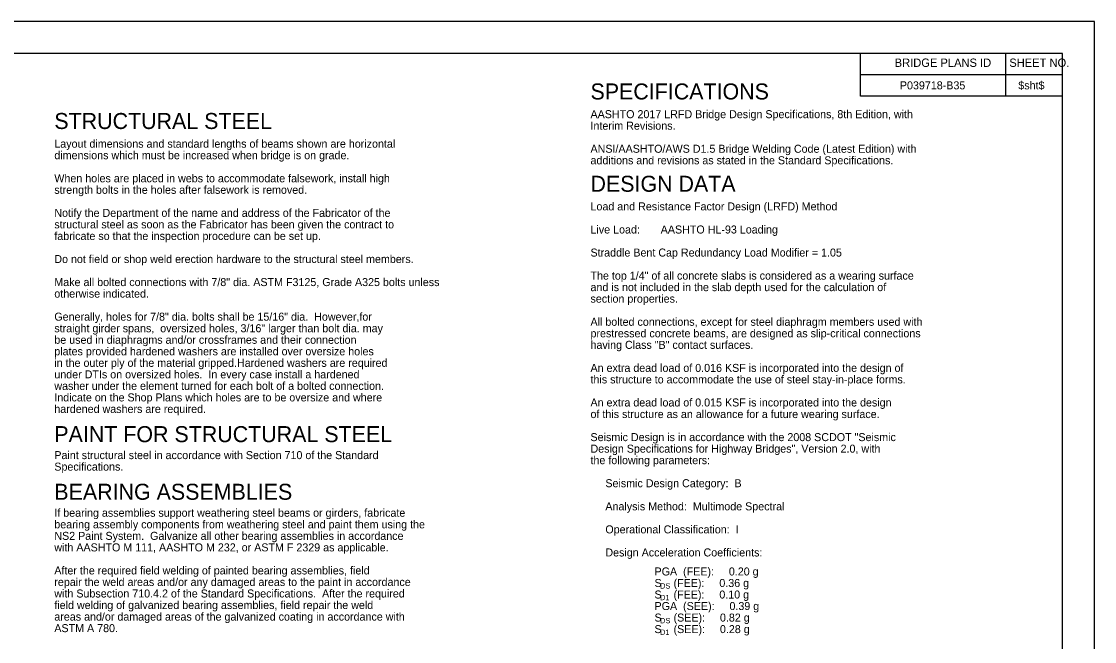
# Model space of a CAD drawing. Extents: x -1.3 to 34.8, y 0.8 to 22.8.
# Drawn here: x 17.92 to 34.68, y 13.14 to 22.82 of the extents above; entities that cross this region are included whole.
import ezdxf

# ---------------------------------------------------------------- set-up
doc = ezdxf.new("R2010")
doc.units = 0
for name, color, linetype in [('BR_BORDER LINES', 7, 'Continuous'), ('BR_TEXT', 7, 'Continuous'), ('Level 31', 7, 'Continuous')]:
    doc.layers.add(name, color=color, linetype=linetype)

msp = doc.modelspace()

# ---------------------------------------------------------------- linework, layer by layer
at = {"layer": 'BR_BORDER LINES'}
for p, q in [((34.177, 22.318), (0.511, 22.318)), ((31.024, 21.651), (31.024, 22.318)), ((33.291, 21.651), (33.291, 22.318)), ((34.177, 1.318), (34.177, 22.318)), ((31.024, 21.989), (34.177, 21.989)), ((33.291, 21.989), (34.177, 21.989)), ((34.177, 21.651), (31.024, 21.651))]:
    msp.add_line(p, q, dxfattribs=at)
at = {"layer": 'Level 31'}
msp.add_lwpolyline([(-1.323, 0.818), (34.677, 0.818), (34.677, 22.818), (-1.323, 22.818)], close=True, dxfattribs=at)

# ---------------------------------------------------------------- texts
at = {"layer": 'BR_TEXT'}
for s, height, p in [('BRIDGE PLANS ID', 0.13, (31.556, 22.109)), ('SHEET NO.', 0.13, (33.346, 22.109)), ('SPECIFICATIONS', 0.25, (26.805, 21.6)), ('P039718-B35', 0.125, (31.637, 21.758)), ('$sht$', 0.125, (33.487, 21.758)), ('STRUCTURAL STEEL', 0.25, (18.431, 21.139)), ('AASHTO 2017 LRFD Bridge Design Specifications, 8th Edition, with', 0.125, (26.805, 21.308)), ('Interim Revisions. ', 0.125, (26.805, 21.128)), ('Layout dimensions and standard lengths of beams shown are horizontal ', 0.125, (18.431, 20.847)), ('dimensions which must be increased when bridge is on grade.', 0.125, (18.431, 20.667)), ('ANSI/AASHTO/AWS D1.5 Bridge Welding Code (Latest Edition) with', 0.125, (26.805, 20.768)), ('additions and revisions as stated in the Standard Specifications.', 0.125, (26.805, 20.588)), ('When holes are placed in webs to accommodate falsework, install high', 0.125, (18.431, 20.307)), ('DESIGN DATA', 0.25, (26.805, 20.159)), ('strength bolts in the holes after falsework is removed.', 0.125, (18.431, 20.127)), ('Load and Resistance Factor Design (LRFD) Method', 0.125, (26.805, 19.868)), ('Notify the Department of the name and address of the Fabricator of the ', 0.125, (18.431, 19.767)), ('structural steel as soon as the Fabricator has been given the contract to ', 0.125, (18.431, 19.587)), ('Live Load:       AASHTO HL-93 Loading ', 0.125, (26.805, 19.507)), ('fabricate so that the inspection procedure can be set up.', 0.125, (18.431, 19.406)), ('Straddle Bent Cap Redundancy Load Modifier = 1.05', 0.125, (26.805, 19.147)), ('Do not field or shop weld erection hardware to the structural steel members. ', 0.125, (18.431, 19.046)), ('Make all bolted connections with 7/8" dia. ASTM F3125, Grade A325 bolts unless', 0.125, (18.431, 18.686)), ('The top 1/4" of all concrete slabs is considered as a wearing surface ', 0.125, (26.805, 18.787)), ('otherwise indicated.', 0.125, (18.431, 18.506)), ('and is not included in the slab depth used for the calculation of ', 0.125, (26.805, 18.607)), ('section properties.', 0.125, (26.805, 18.427)), ('Generally, holes for 7/8" dia. bolts shall be 15/16" dia.  However,for ', 0.125, (18.431, 18.146)), ('All bolted connections, except for steel diaphragm members used with', 0.125, (26.805, 18.066)), ('straight girder spans,  oversized holes, 3/16" larger than bolt dia. may ', 0.125, (18.431, 17.965)), ('prestressed concrete beams, are designed as slip-critical connections', 0.125, (26.805, 17.886)), ('be used in diaphragms and/or crossframes and their connection ', 0.125, (18.431, 17.785)), ('having Class "B" contact surfaces.', 0.125, (26.805, 17.706)), ('plates provided hardened washers are installed over oversize holes', 0.125, (18.431, 17.605)), ('in the outer ply of the material gripped.Hardened washers are required', 0.125, (18.431, 17.425)), ('An extra dead load of 0.016 KSF is incorporated into the design of ', 0.125, (26.805, 17.346)), ('under DTIs on oversized holes.  In every case install a hardened ', 0.125, (18.431, 17.245)), ('this structure to accommodate the use of steel stay-in-place forms.', 0.125, (26.805, 17.166)), ('washer under the element turned for each bolt of a bolted connection.  ', 0.125, (18.431, 17.065)), ('Indicate on the Shop Plans which holes are to be oversize and where ', 0.125, (18.431, 16.885)), ('An extra dead load of 0.015 KSF is incorporated into the design', 0.125, (26.805, 16.806)), ('hardened washers are required. ', 0.125, (18.431, 16.705)), ('of this structure as an allowance for a future wearing surface.', 0.125, (26.805, 16.625)), ('PAINT FOR STRUCTURAL STEEL', 0.25, (18.431, 16.249)), ('Seismic Design is in accordance with the 2008 SCDOT "Seismic', 0.125, (26.805, 16.265)), ('Paint structural steel in accordance with Section 710 of the Standard ', 0.125, (18.431, 15.984)), ('Design Specifications for Highway Bridges", Version 2.0, with', 0.125, (26.805, 16.085)), ('Specifications.', 0.125, (18.431, 15.804)), ('the following parameters:', 0.125, (26.805, 15.905)), ('BEARING ASSEMBLIES', 0.25, (18.431, 15.349)), ('     Seismic Design Category:  B', 0.125, (26.805, 15.545)), ('     Analysis Method:  Multimode Spectral', 0.125, (26.805, 15.184)), ('If bearing assemblies support weathering steel beams or girders, fabricate ', 0.125, (18.431, 15.084)), ('bearing assembly components from weathering steel and paint them using the ', 0.125, (18.431, 14.903)), ('     Operational Classification:  I', 0.125, (26.805, 14.824)), ('NS2 Paint System.  Galvanize all other bearing assemblies in accordance ', 0.125, (18.431, 14.723)), ('with AASHTO M 111, AASHTO M 232, or ASTM F 2329 as applicable. ', 0.125, (18.431, 14.543)), ('     Design Acceleration Coefficients:', 0.125, (26.805, 14.464)), ('After the required field welding of painted bearing assemblies, field ', 0.125, (18.431, 14.183)), ('PGA  (FEE):     0.20 g', 0.125, (27.805, 14.167)), ('repair the weld areas and/or any damaged areas to the paint in accordance ', 0.125, (18.431, 14.003)), ('S    (FEE):     0.36 g', 0.125, (27.805, 13.987)), ('with Subsection 710.4.2 of the Standard Specifications.  After the required ', 0.125, (18.431, 13.823)), ('S    (FEE):     0.10 g', 0.125, (27.805, 13.807)), ('DS', 0.0833, (27.892, 13.962)), ('field welding of galvanized bearing assemblies, field repair the weld ', 0.125, (18.431, 13.643)), ('PGA  (SEE):     0.39 g', 0.125, (27.805, 13.627)), ('D1', 0.0833, (27.892, 13.781)), ('areas and/or damaged areas of the galvanized coating in accordance with ', 0.125, (18.431, 13.462)), ('S    (SEE):     0.82 g', 0.125, (27.805, 13.447)), ('ASTM A 780.', 0.125, (18.431, 13.282)), ('DS', 0.0833, (27.892, 13.42)), ('S    (SEE):     0.28 g', 0.125, (27.805, 13.267)), ('D1', 0.0833, (27.892, 13.239))]:
    msp.add_text(s, height=height, dxfattribs=at).set_placement(p)

doc.saveas('drawing.dxf')
